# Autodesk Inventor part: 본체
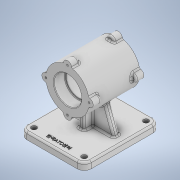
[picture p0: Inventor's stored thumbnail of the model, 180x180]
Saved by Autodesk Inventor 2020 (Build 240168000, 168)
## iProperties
Created: 2022-11
Part Number: 본체
Material: 일반
Document SubType Name: Modeling
Designer: owner
Density: 1 g/cm^3
Appearance: 기본값
Author: owner
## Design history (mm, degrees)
sketch "스케치1"
  geometry: L1 (55, -65)-(-55, -65); L2 (-55, -65)-(-55, 65); L3 (-55, 65)-(55, 65); L4 (55, 65)-(55, -65); L5 (55, -65)-(-55, 65); L6 (-55, -65)-(55, 65); 1 further point
  constraints: 12 end point, 2 midpoint, 2 parallel, 1 horizontal, 1 perpendicular
  dimensions: "d0" = 110 distance of L2.end L3.end; "d1" = 130 distance of L1.end L2.end
extrude "돌출1" new body sketch "스케치1" distance "d2" = 12; taper "d3" = 0 deg
node "작업 평면1"
sketch "스케치2"
  geometry: L1 (0, 0)-(110, 0) reference; C1 r 37 at (55, 82); 2 further points
  constraints: 1 centre point, 1 midpoint, 1 vertical alignment
  dimensions: "d5" = 74 diameter of C1; "d6" = 82 distance from line of L1 C1.centre
extrude "돌출2" join sketch "스케치2" stored distance "d7" = 87; taper "d8" = 0 deg
sketch "스케치3"
  geometry: A1 r 7 centre (0, 37) between (6.969, 36.338) and (-6.969, 36.338); A2 r 7 centre (37, 0) between (36.338, -6.969) and (36.338, 6.969); A3 r 7 centre (0, -37) between (-6.969, -36.338) and (6.969, -36.338); A4 r 7 centre (-37, 0) between (-36.338, 6.969) and (-36.338, -6.969); 2 further points
  constraints: 8 point on circle, 4 centre point, 2 horizontal alignment, 2 vertical alignment, 13 other
  dimensions: "d9" = 14 diameter of A1; "d10" = 14 diameter of A2; "d11" = 14 diameter of A3; "d12" = 14 diameter of A4
extrude "돌출3" join sketch "스케치3" distance "d13" = 14; taper "d14" = 0 deg
sketch "스케치4"
  geometry: A1 r 37 centre (55, 82) between (91.338, 88.969) and (61.969, 118.338) reference; 2 further points
  constraints: 1 coincident
hole "구멍1" sketch "스케치4" at (55, 82) diameter "d15" = 47; stored, may be unused: countersink angle "d19" = 90 deg, drill point angle "d21" = 0 deg; dims "d16" = 8, "d17" = 4, "d18" = 2, "d20" = 19
sketch "스케치6"
  geometry: A1 r 37 centre (-55, 82) between (-18.662, 88.969) and (-48.031, 118.338) reference; 2 further points
  constraints: 1 coincident
hole "구멍2" sketch "스케치6" at (-55, 82) diameter "d22" = 42; stored, may be unused: countersink angle "d26" = 90 deg, drill point angle "d28" = 0 deg; dims "d23" = 8, "d24" = 47, "d25" = 19, "d27" = 19
sketch "스케치7"
  geometry: L1 (110, 12)-(0, 12) reference; L2 (110, 0)-(110, 12) reference; L3 (0, 0)-(0, 12) reference; L4 (14, 12)-(29.664, 55.036); L5 (96, 12)-(80.336, 55.036); A1 r 37 centre (55, 82) between (18.662, 75.031) and (48.031, 45.662) reference; A2 r 37 centre (55, 82) between (61.969, 45.662) and (91.338, 75.031) reference; A3 r 37 centre (55, 82) between (48.031, 45.662) and (61.969, 45.662) reference; 1 further point
  constraints: 4 end point, 2 point on circle, 2 point on line, 1 equal length
  dimensions: "d29" = 14 distance from line of L4.start L3; "d30" = 110 deg angle of L1 L4; "d31" = 110 deg angle of L1 L5
extrude "돌출4" join sketch "스케치7" stored distance "d32" = 10; taper "d33" = 0 deg
node "작업 평면2"
sketch "스케치8"
  geometry: L1 (30.5, 45)-(89.5, 45) reference; L2 (130, 12)-(0, 12) reference; L3 (40, 12)-(40, 45); L4 (65, 55.036)-(55, 55.036) reference; L5 (65, 12)-(65, 55.036) reference; L6 (55, 12)-(65, 12) reference; L7 (55, 55.036)-(55, 12) reference; L8 (60, 151.2)-(60, -25.2) reference; 1 further point
  constraints: 2 end point, 2 point on line, 1 perpendicular
  dimensions: "d35" = 20 distance from line of L3.start L8
feature "리브1" sketch "스케치8" dims "d36" = 1, "d37" = 10, "d38" = 0, "d39" = 0, "d40" = 1, "d41" = 1
fillet "모깎기1" dims "d42" = 12
sketch "스케치9"
  geometry: A1 r 12 centre (-43, 53) between (-43, 65) and (-55, 53) reference; 2 further points
  constraints: 1 coincident
hole "구멍3" sketch "스케치9" at (-43, 53) diameter "d43" = 9; stored, may be unused: countersink angle "d47" = 90 deg, drill point angle "d49" = 0 deg; dims "d44" = 8, "d45" = 47, "d46" = 19, "d48" = 12
sketch "스케치10"
  geometry: A1 r 12 centre (-43, -53) between (-55, -53) and (-43, -65) reference; 2 further points
  constraints: 1 coincident
hole "구멍4" sketch "스케치10" at (-43, -53) diameter "d50" = 9; stored, may be unused: countersink angle "d54" = 90 deg, drill point angle "d56" = 0 deg; dims "d51" = 8, "d52" = 47, "d53" = 19, "d55" = 12
sketch "스케치11"
  geometry: A1 r 12 centre (43, -53) between (43, -65) and (55, -53) reference; 2 further points
  constraints: 1 coincident
hole "구멍5" sketch "스케치11" at (43, -53) diameter "d57" = 9; stored, may be unused: countersink angle "d61" = 90 deg, drill point angle "d63" = 0 deg; dims "d58" = 8, "d59" = 47, "d60" = 19, "d62" = 12
sketch "스케치12"
  geometry: A1 r 12 centre (43, 53) between (55, 53) and (43, 65) reference; 2 further points
  constraints: 1 coincident
hole "구멍6" sketch "스케치12" at (43, 53) diameter "d64" = 9; stored, may be unused: countersink angle "d68" = 90 deg, drill point angle "d70" = 0 deg; dims "d65" = 8, "d66" = 47, "d67" = 19, "d69" = 12
sketch "스케치13"
  geometry: A1 r 7 centre (55, 119) between (61.969, 118.338) and (48.031, 118.338) reference; 2 further points
  constraints: 1 coincident
hole "구멍7" sketch "스케치13" at (55, 119) diameter "d71" = 3.242; stored, may be unused: countersink angle "d75" = 90 deg, drill point angle "d77" = 118 deg; dims "d72" = 8, "d73" = 47, "d74" = 19, "d76" = 10
fillet "모깎기2" dims "d81" = 1
chamfer "모따기1" distance "d82" = 1; stored, may be unused: second distance "d83" = 2, angle "d84" = 45 deg
fillet "모깎기3" dims "d85" = 3
fillet "모깎기4" dims "d86" = 3
fillet "모깎기5" dims "d87" = 3
fillet "모깎기6" dims "d88" = 3
fillet "모깎기7" dims "d89" = 3
fillet "모깎기8" dims "d90" = 3
fillet "모깎기9" dims "d91" = 3
sketch "스케치14"
  geometry: L1 (-55, 53)-(-55, -53) reference; C1 r 4.5 at (-43, -53) reference; 2 further points
  constraints: 1 horizontal alignment, 1 other
  dimensions: "d92" = 55 distance from line of L1 point (0, -53)
feature "엠보싱1" sketch "스케치14" dims "d0" = 110, "d1" = 130, "d93" = 0.5, "d94" = 0
node "솔리드1"
mirror "미러1"
mirror "미러2"
pattern_circular "원형 패턴1" dims angle "d79" = 360 deg
mirror "미러3"
node "투영된 루프1"
feature "A9D066F2-1C7D-4E18-AEED-F7BC21143FA4" dims "d15" = 47, "d16" = 8, "d17" = 4, "d18" = 2, "d19" = 90 deg, "d20" = 19, "d21" = 0
other parameters: "d34" = -55
